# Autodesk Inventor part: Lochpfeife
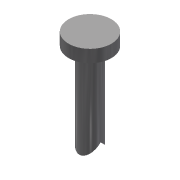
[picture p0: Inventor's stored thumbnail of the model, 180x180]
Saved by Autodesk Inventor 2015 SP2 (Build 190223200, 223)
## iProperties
Created: 2017-07
Material: 115CrV5 (Silberstahl)
Document SubType Name: Modeling
Designer: UR
Density: 7.73 g/cm^3
Appearance: Halbpoliert
Part Number: Lochpfeife
Mass: 8.58358 g
Surface Area: 8.58243 cm^2
Volume: 1.11042 cm^3
Author: UR
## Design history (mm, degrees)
sketch "Skizze1"
  geometry: L1 (0, 0)-(3, 0); L2 (3, 0)-(3, 25); L3 (3, 25)-(6, 25); L4 (6, 25)-(6, 28.5); L5 (6, 28.5)-(0, 28.5); L6 (0, 28.5)-(0, 0)
  constraints: 12 end point, 5 perpendicular, 1 horizontal
  dimensions: "d0" = 6 diameter of L2 L6; "d1" = 12 diameter of L4 L6; "d2" = 28.5 distance between parallel lines of L1 L5; "d3" = 3.5 distance between parallel lines of L3 L5
revolve "Umdrehung1" sketch "Skizze1" stored, may be unused: angle "d4" = 90 deg
sketch "Skizze2"
  geometry: L1 (-3, 0)-(3, 0) reference; L2 (-3, 0)-(0, 3); L3 (0, 3)-(3, 0); L4 (0, 0)-(0, 3)
  constraints: 6 end point, 1 perpendicular, 1 vertical
extrude "Extrusion1" cut sketch "Skizze2" stored distance "d5" = 10; taper "d6" = 0 deg
node "Volumenkörper1"
